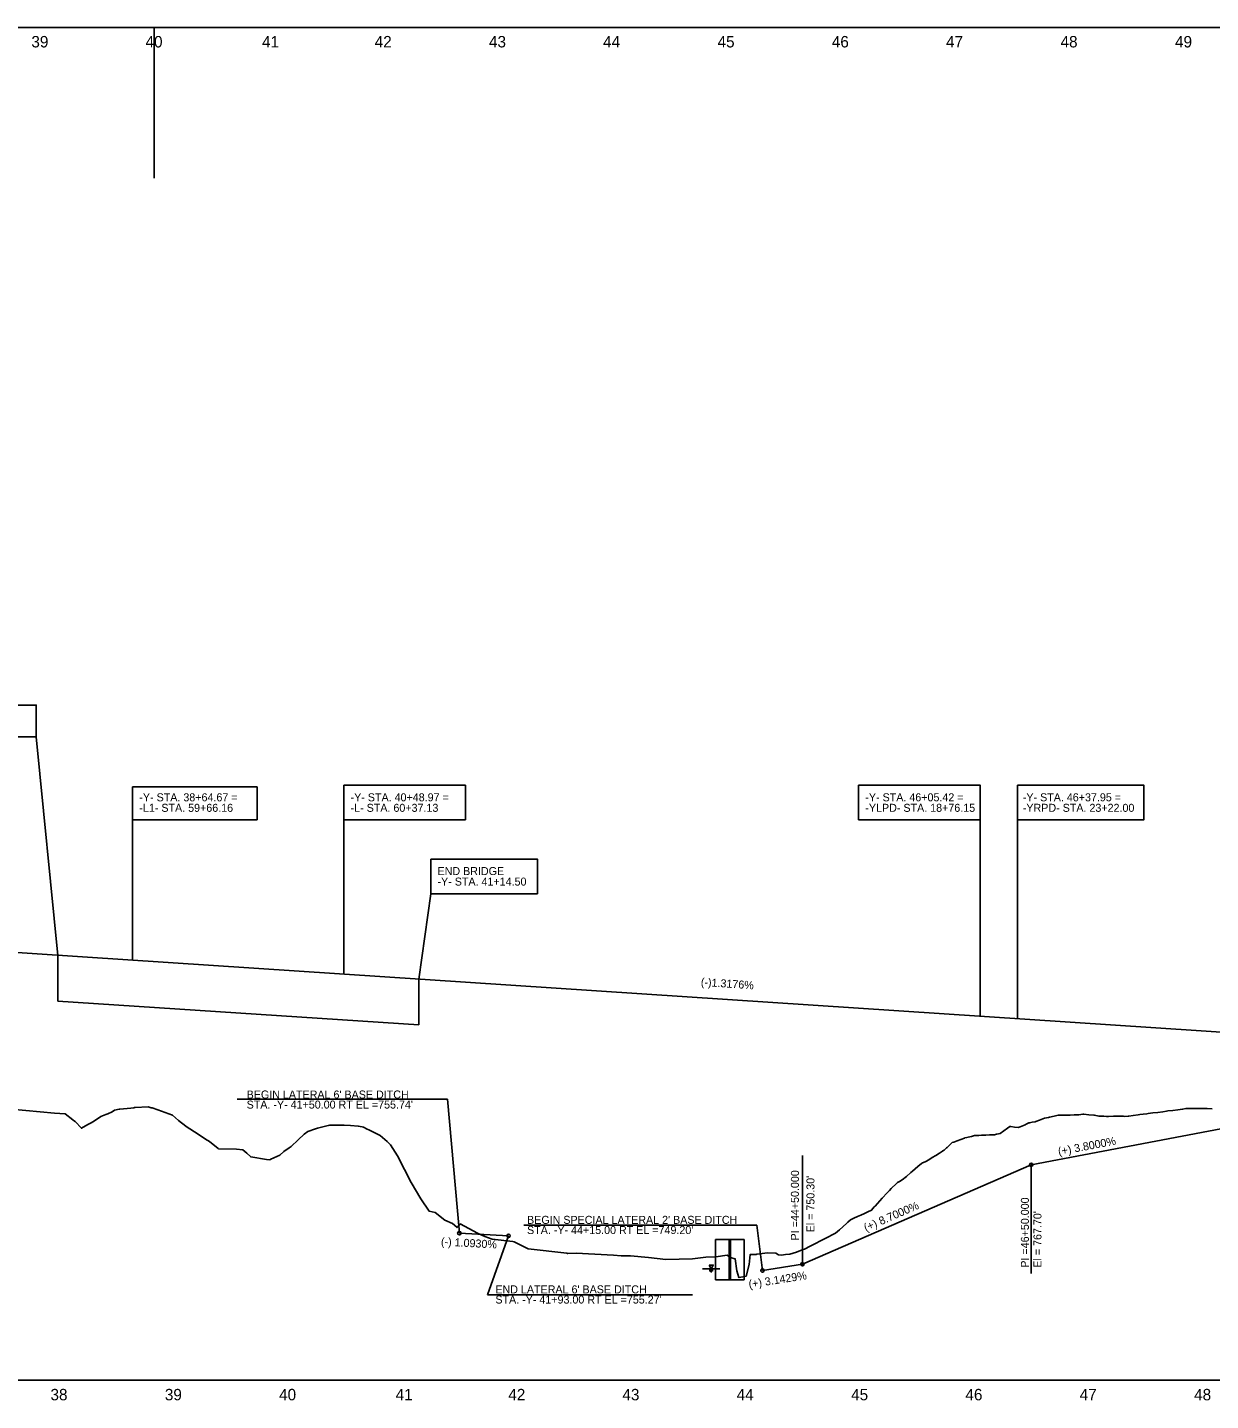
# Model space of a CAD drawing. Extents: x 579185 to 595036, y -53221 to -44640.
# Drawn here: x 582099 to 583133, y -47238 to -46038 of the extents above; entities that cross this region are included whole.
import ezdxf

# ---------------------------------------------------------------- set-up
doc = ezdxf.new("R2010")
doc.units = 0
for name, color, linetype in [('Default', 7, 'Continuous'), ('Exist Profile Cell', 7, 'Continuous'), ('Exist Vertical Profile Ground Line', 7, 'Continuous'), ('Exist Vertical Profile Horizontal Axis Label Major', 7, 'Continuous'), ('Prop Grid Mask', 7, 'Continuous'), ('Prop PFL Text', 7, 'Continuous'), ('Prop Roadway Bridge', 7, 'Continuous'), ('Prop Roadway Culvert', 7, 'Continuous'), ('Prop Vertical Profile Curve Label', 7, 'Continuous'), ('Prop Vertical Profile Ditch Grade Right', 7, 'Continuous'), ('Prop Vertical Profile Ditch Grade Right Label', 7, 'Continuous'), ('Prop Vertical Profile Grade', 7, 'Continuous'), ('Prop Vertical Profile Grade Label', 7, 'Continuous'), ('Prop VPI Ditch Grade Right Label', 7, 'Continuous'), ('Prop VPI Label', 7, 'Continuous')]:
    doc.layers.add(name, color=color, linetype=linetype)

msp = doc.modelspace()

# ---------------------------------------------------------------- linework, layer by layer
at = {"layer": 'Default'}
msp.add_line((582209.4, -46169.4), (582209.4, -46037.5), dxfattribs=at)
at = {"layer": 'Exist Profile Cell'}
for p, q in [((579243, -46037.5), (595036.4, -46037.5)), ((579326.2, -47220.5), (584953.7, -47220.5))]:
    msp.add_line(p, q, dxfattribs=at)
at = {"layer": 'Exist Vertical Profile Ground Line'}
for points in [[(582071.8, -46982.3), (582122.3, -46987), (582131.4, -46987.6), (582138.3, -46992.6), (582139.8, -46993.8), (582140.4, -46994.3), (582145.7, -47000.1), (582151.3, -46996.9), (582154.4, -46995.3), (582157.3, -46993.5), (582162.7, -46989.9), (582167, -46988.2), (582168.7, -46987.6), (582172.6, -46985.7), (582174.8, -46984.4), (582178.6, -46983.5), (582179.2, -46983.4), (582189, -46982.4), (582191.7, -46982.1), (582192.1, -46982), (582192.7, -46982), (582204, -46981.4), (582206.8, -46982.1), (582207.6, -46982.3), (582212.6, -46984.1), (582225.4, -46988.7), (582230.5, -46993.2), (582237, -46998.2), (582237.4, -46998.5), (582247.7, -47005.4), (582254.1, -47009.7), (582257.8, -47011.6), (582265.2, -47017.9), (582265.7, -47018), (582281.3, -47018.3), (582286.9, -47019.1), (582290.3, -47022), (582293.8, -47025.2), (582307.5, -47027.3), (582310.6, -47027.7), (582311.5, -47027.2), (582319.3, -47023.7), (582322.8, -47020.4), (582327.5, -47017.3), (582329.1, -47016.1), (582335.4, -47010.2), (582340.4, -47005.3), (582343.7, -47002.8), (582350.4, -47000.5), (582351.2, -47000.3), (582352.3, -47000), (582359.1, -46998.4), (582361.6, -46997.7), (582362.6, -46997.4), (582366.8, -46997.4), (582375.4, -46997.4), (582381.1, -46997.8), (582387.8, -46998.2), (582391.3, -46999), (582392.3, -46999.2), (582395.7, -47001), (582397.1, -47001.6), (582407, -47006.3), (582413.2, -47011.7), (582415.9, -47014.5), (582422, -47024.2), (582428.2, -47036.1), (582434.2, -47047.4), (582442.6, -47061.9), (582449.7, -47072.5), (582455.1, -47073.8), (582463.5, -47080.5), (582470.3, -47083.4), (582471.9, -47084.8), (582474.2, -47087), (582476, -47084.9), (582477, -47083.7), (582492.1, -47091.8), (582498.4, -47094.7), (582504.9, -47097.1)], [(582946, -47005.3), (582946.3, -47005.2), (582949.1, -47004.7), (582952.2, -47002.4), (582955.4, -47000), (582957.6, -46998.6), (582958.5, -46998.7), (582961.6, -46999.1), (582964.7, -46999.3), (582966.6, -46999), (582967.9, -46998.4), (582971, -46997), (582971.9, -46996.6), (582974.1, -46995.5), (582974.8, -46995.4), (582977.2, -46994.9), (582979.8, -46994.4), (582980.4, -46994.2), (582983.5, -46993), (582987.8, -46991.4), (582991.4, -46990.6), (582992.1, -46990.4), (582996.4, -46989.5), (582999.7, -46988.8), (583000.8, -46988.8), (583005.1, -46988.7), (583009.4, -46988.6), (583010.4, -46988.6), (583013.7, -46988.5), (583017.3, -46988.5), (583018, -46988.3), (583021.3, -46987.8), (583022.3, -46987.9), (583026.6, -46988.3), (583030.9, -46988.7), (583031.7, -46988.8), (583035.3, -46989.4), (583035.8, -46989.4), (583039.6, -46989.6), (583042, -46989.8), (583043.9, -46989.7), (583048.2, -46989.5), (583049.6, -46989.5), (583052.5, -46989.5), (583056.8, -46989.6), (583058.1, -46989.7), (583061.1, -46989.5), (583061.6, -46989.5), (583065.5, -46989), (583069.8, -46988.4), (583071.1, -46988.2), (583074.1, -46987.8), (583077.2, -46987.4), (583078.4, -46987.3), (583080.4, -46987), (583082.7, -46986.7), (583087, -46986.2), (583091.3, -46985.6), (583094.4, -46985.2), (583095.7, -46985), (583100, -46984.5), (583104.3, -46983.9), (583108.6, -46983.3), (583108.9, -46983.3), (583111.3, -46982.9), (583112.9, -46982.9), (583113.6, -46982.9), (583117.2, -46982.9), (583121.5, -46982.9), (583125.3, -46982.9), (583125.9, -46982.9), (583130.2, -46982.9), (583134.5, -46983)], [(582504.9, -47097.1), (582522.9, -47099), (582524, -47099.4), (582536.4, -47105.5), (582570.1, -47109.4), (582570.7, -47109.5), (582571.2, -47109.5), (582578.3, -47109.2), (582611.1, -47111), (582617.7, -47111.7), (582625.8, -47111.8), (582641.6, -47113), (582656.8, -47114.8), (582680.2, -47114.4), (582691.8, -47112.9), (582700.6, -47112.5), (582710.3, -47111), (582713.1, -47113.1), (582717.4, -47114.4), (582718.9, -47124.7), (582720.6, -47130.7), (582724.1, -47129.9), (582727, -47129.4), (582729.5, -47119.1), (582730.5, -47110.4), (582735.7, -47110.5), (582736.4, -47110.2), (582745.5, -47109.1), (582752.9, -47109.4), (582755.4, -47110.7), (582757.9, -47111), (582761.5, -47110.5), (582765.1, -47110.3), (582771, -47108.4), (582776, -47106.5), (582777.9, -47105.8), (582779.1, -47105.1), (582781.7, -47103.8), (582783.5, -47102.9), (582796, -47096.6), (582805.2, -47091.9), (582808.5, -47089), (582814.7, -47083.5), (582816, -47082.3), (582818.1, -47080.1), (582821, -47078.8), (582824.4, -47077.3), (582827.2, -47076), (582828.4, -47075.5), (582829.3, -47075.2), (582833.5, -47073.1), (582836.6, -47071.6), (582839, -47068.9), (582839.7, -47068.1), (582846, -47061.2), (582850.2, -47056.6), (582852.2, -47054.4), (582853.7, -47052.8), (582858.5, -47048.3), (582859.4, -47047.5), (582861.7, -47046.3), (582864.7, -47044.2), (582866, -47043.3), (582867.1, -47042.4), (582871, -47038.8), (582872.4, -47037.5), (582877.2, -47033.5), (582880.4, -47030.8), (582881.1, -47030.2), (582883.5, -47029.5), (582884.2, -47029.3), (582886.6, -47027.8), (582889.7, -47025.8), (582892.9, -47023.8), (582896, -47021.8), (582898.8, -47020), (582899.1, -47019.9), (582900.2, -47019.2), (582902.2, -47017.3), (582902.6, -47017), (582905.4, -47014.4), (582906.6, -47013.2), (582907.2, -47012.7), (582908.5, -47012.2), (582911.6, -47011), (582914.7, -47009.9), (582917.9, -47008.7), (582918.3, -47008.5), (582919.8, -47008.3), (582921, -47008), (582924.1, -47007.2), (582926.6, -47006.5), (582927.2, -47006.5), (582930.4, -47006.3), (582932.9, -47006.1), (582933.5, -47006.1), (582936.6, -47006), (582939.7, -47005.9), (582942.9, -47005.8), (582944, -47005.8), (582946, -47005.3)]]:
    msp.add_lwpolyline(points, dxfattribs=at)
at = {"layer": 'Prop Grid Mask'}
for points in [[(582005.4, -46630.1), (582106.2, -46630.1), (582106.2, -46657.8), (582005.4, -46657.8)], [(582190.5, -46701.6), (582299.4, -46701.6), (582299.4, -46730.4), (582190.5, -46730.4)], [(582375.2, -46700.2), (582481.5, -46700.2), (582481.5, -46730.4), (582375.2, -46730.4)], [(582825.3, -46700.2), (582931.7, -46700.2), (582931.7, -46730.4), (582825.3, -46730.4)], [(582964.2, -46700.2), (583074.8, -46700.2), (583074.8, -46730.4), (582964.2, -46730.4)], [(582451.2, -46764.7), (582544.5, -46764.7), (582544.5, -46795), (582451.2, -46795)]]:
    msp.add_lwpolyline(points, close=True, dxfattribs=at)
at = {"layer": 'Prop PFL Text'}
for p, q in [((582688.9, -47122.9), (582703.9, -47122.9)), ((582694.6, -47124.5), (582698.1, -47124.5)), ((582695.3, -47125.2), (582697.4, -47125.2)), ((582696, -47126), (582696.7, -47126))]:
    msp.add_line(p, q, dxfattribs=at)
msp.add_lwpolyline([(582694.7, -47119.7), (582698.2, -47119.7), (582696.4, -47122.9)], close=True, dxfattribs=at)
at = {"layer": 'Prop Roadway Bridge'}
for p, q in [((582125.2, -46889), (582125.2, -46848.9)), ((582440.7, -46909.8), (582440.7, -46869.7)), ((582125.2, -46889), (582440.7, -46909.8))]:
    msp.add_line(p, q, dxfattribs=at)
at = {"layer": 'Prop Roadway Culvert'}
for p, q in [((582700.2, -47132.5), (582700.2, -47097.5)), ((582700.2, -47097.5), (582725.2, -47097.5)), ((582712.2, -47132.5), (582712.2, -47097.5)), ((582713.2, -47132.5), (582713.2, -47097.5)), ((582725.2, -47132.5), (582725.2, -47097.5)), ((582700.2, -47132.5), (582725.2, -47132.5))]:
    msp.add_line(p, q, dxfattribs=at)
at = {"layer": 'Prop Vertical Profile Curve Label'}
for p, q in [((582125.2, -46848.9), (582106.2, -46657.8)), ((582190.5, -46853.2), (582190.5, -46730.4)), ((582375.2, -46865.4), (582375.2, -46730.4)), ((582931.7, -46902), (582931.7, -46730.4)), ((582964.2, -46904.2), (582964.2, -46730.4)), ((582440.7, -46869.7), (582451.2, -46795))]:
    msp.add_line(p, q, dxfattribs=at)
at = {"layer": 'Prop Vertical Profile Ditch Grade Right'}
msp.add_line((582476.2, -47091.8), (582519.2, -47094.2), dxfattribs=at)
msp.add_lwpolyline([(582741.2, -47124.5), (582776.2, -47119), (582976.2, -47032), (583326.2, -46965.5)], dxfattribs=at)
at = {"layer": 'Prop Vertical Profile Ditch Grade Right Label'}
for p, q in [((582281.9, -46974.8), (582465.8, -46974.8)), ((582465.8, -46974.8), (582476.2, -47091.8)), ((582776.3, -47024), (582776.2, -47119)), ((582976.2, -47032), (582976.2, -47127.1)), ((582532.7, -47084.8), (582736.3, -47084.8)), ((582741.2, -47124.5), (582736.3, -47084.8)), ((582519.2, -47094.2), (582500.9, -47145.8)), ((582500.9, -47145.8), (582680.1, -47145.8))]:
    msp.add_line(p, q, dxfattribs=at)
at = {"layer": 'Prop Vertical Profile Grade'}
msp.add_line((581761.2, -46824.9), (583296.2, -46926.1), dxfattribs=at)
at = {"layer": 'Prop VPI Ditch Grade Right Label'}
for centre in [(582976.2, -47032), (582476.2, -47091.8), (582519.2, -47094.2), (582741.2, -47124.5), (582776.2, -47119)]:
    msp.add_circle(centre, 1.5, dxfattribs=at)

# ---------------------------------------------------------------- texts
at = {"layer": 'Exist Vertical Profile Horizontal Axis Label Major'}
for s, p in [('39', (582102, -46055)), ('40', (582201.8, -46055)), ('41', (582303.7, -46055)), ('42', (582402.2, -46055)), ('43', (582502.1, -46055)), ('44', (582601.9, -46055)), ('45', (582702, -46055)), ('46', (582801.9, -46055)), ('47', (582901.8, -46055)), ('48', (583001.9, -46055)), ('49', (583102, -46055)), ('38', (582118.7, -47238)), ('39', (582218.7, -47238)), ('40', (582318.6, -47238)), ('41', (582420.5, -47238)), ('42', (582519, -47238)), ('43', (582618.8, -47238)), ('44', (582718.7, -47238)), ('45', (582818.8, -47238)), ('46', (582918.7, -47238)), ('47', (583018.6, -47238)), ('48', (583118.7, -47238))]:
    msp.add_text(s, height=10, dxfattribs=at).set_placement(p)
at = {"layer": 'Prop Vertical Profile Ditch Grade Right'}
for s, p in [("BEGIN LATERAL 6' BASE DITCH", (582290.2, -46974.1)), ("STA. -Y- 41+50.00 RT EL =755.74'", (582290.2, -46982.9)), ("BEGIN SPECIAL LATERAL 2' BASE DITCH", (582535.4, -47083.7)), ("STA. -Y- 44+15.00 RT EL =749.20'", (582535.4, -47092.6)), ("END LATERAL 6' BASE DITCH", (582507.7, -47144.5)), ("STA. -Y- 41+93.00 RT EL =755.27'", (582507.7, -47153.4))]:
    msp.add_text(s, height=7, dxfattribs=at).set_placement(p)
for s, rotation, p in [('(+) 3.8000%', 10.758, (583000.4, -47023.9)), ('PI =44+50.000', 90, (582773.1, -47098.2)), ("El = 750.30'", 90, (582786.7, -47091.1)), ('(+) 8.7000%', 23.509, (582831.7, -47090.6)), ('PI =46+50.000', 90, (582974.2, -47122)), ("El = 767.70'", 90, (582985.2, -47122)), ('(-) 1.0930%', 356.8718, (582460, -47102.6)), ('(+) 3.1429%', 8.9306, (582729.7, -47140))]:
    msp.add_text(s, height=7, rotation=rotation, dxfattribs=at).set_placement(p)
at = {"layer": 'Prop Vertical Profile Grade Label'}
msp.add_text('(-)1.3176%', height=7, rotation=356.2308, dxfattribs=at).set_placement((582687.2, -46875.6))
at = {"layer": 'Prop VPI Label'}
for s, p in [('-Y- STA. 38+64.67 =', (582196.4, -46714.2)), ('-L1- STA. 59+66.16', (582196.4, -46723.4)), ('-Y- STA. 40+48.97 =', (582381.1, -46714.2)), ('-L- STA. 60+37.13', (582381.1, -46723.4)), ('-Y- STA. 46+05.42 =', (582831.2, -46714.2)), ('-YLPD- STA. 18+76.15', (582831.2, -46723.4)), ('-Y- STA. 46+37.95 =', (582968.9, -46714.2)), ('-YRPD- STA. 23+22.00', (582968.9, -46723.4)), ('END BRIDGE ', (582457.1, -46778.7)), ('-Y- STA. 41+14.50', (582457.1, -46787.9))]:
    msp.add_text(s, height=7, dxfattribs=at).set_placement(p)

doc.saveas('drawing.dxf')
